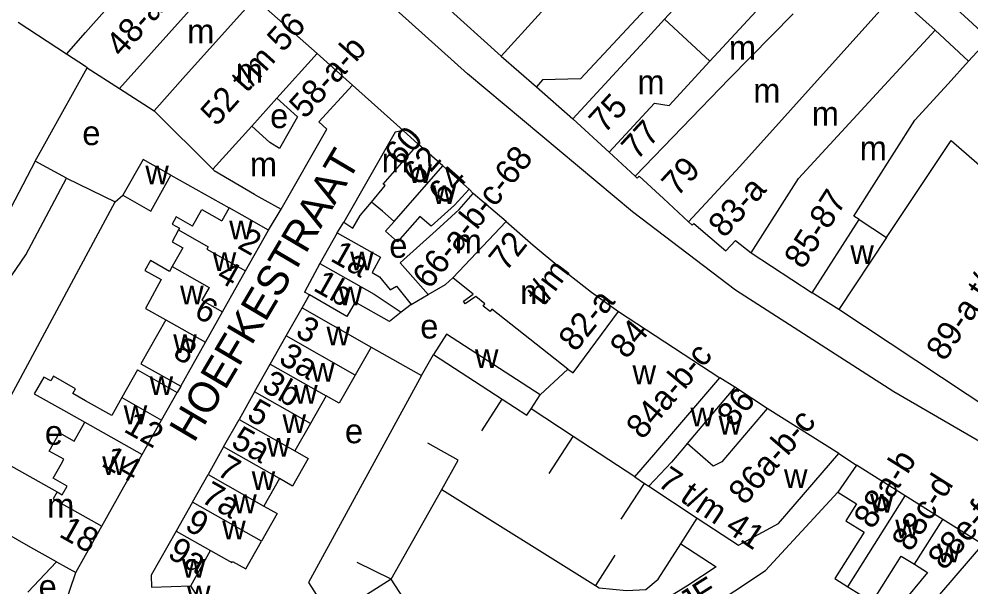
# Model space of a CAD drawing. Extents: x 161141 to 163125, y 381621 to 383200.
# Drawn here: x 161989.1 to 162145.3, y 382642.8 to 382736 of the extents above; entities that cross this region are included whole.
import ezdxf

# ---------------------------------------------------------------- set-up
doc = ezdxf.new("R2010")
doc.units = 0
for name, color, linetype in [('BLT_Basislijn', 7, 'Continuous'), ('BLT_Bebouwing', 7, 'Continuous'), ('BLT_Centroide', 7, 'Continuous'), ('BLT_Huisnummer', 7, 'Continuous'), ('BLT_Huisnummer_ tussenligend', 7, 'Continuous'), ('BLT_Huisnummer_reeks', 7, 'Continuous'), ('BLT_Onderdoorgang_en_onderverdeling', 7, 'Continuous'), ('BLT_Onderverdeling_panden', 7, 'Continuous'), ('BLT_Straatnaam', 7, 'Continuous'), ('BLT_Straatnaam_verkleind', 7, 'Continuous'), ('BLT_Vlakafsluiter', 7, 'Continuous')]:
    doc.layers.add(name, color=color, linetype=linetype)

msp = doc.modelspace()

# ---------------------------------------------------------------- linework, layer by layer
at = {"layer": 'BLT_Basislijn'}
for p, q in [((161996.85, 382730.23), (161988.94, 382735.42)), ((162091.73, 382732.39), (162095.04, 382735.97)), ((162144.96, 382729.08), (162148.35, 382732.76)), ((162068.23, 382729.9), (162074, 382724.85)), ((161991.75, 382712.66), (162000.28, 382728.01)), ((162074, 382724.85), (162079.97, 382719.63)), ((161996.85, 382709.9), (162004.85, 382706.01)), ((162014.02, 382710.39), (162023.55, 382705.02)), ((162004.85, 382706.01), (162006.11, 382707.09)), ((162062.96, 382708.09), (162063.65, 382707.38)), ((162030.05, 382701.36), (162032.1, 382704.77)), ((162041.29, 382700.91), (162042.39, 382702.67)), ((162035.54, 382688.59), (162036.76, 382690.71)), ((162053.43, 382689.16), (162056.23, 382690.77)), ((162046.91, 382682.16), (162055.13, 382677.47)), ((162055.13, 382677.47), (162057.1, 382680.93)), ((162015.62, 382675.73), (162015.05, 382674.72)), ((162065.03, 382668.42), (162068.39, 382673.6)), ((162076.1, 382661.41), (162080.07, 382667.46)), ((162123.64, 382664.66), (162126.56, 382662.79)), ((162087.91, 382653.91), (162091.77, 382659.78)), ((162058.5, 382658.78), (162083.69, 382643.01)), ((162097.73, 382649.88), (162100.42, 382654.1)), ((162097.73, 382649.88), (162103.51, 382646.09)), ((162086.88, 382648.01), (162083.69, 382643.01)), ((161995.24, 382646.9), (161990.55, 382641.9)), ((162050.15, 382644.06), (162044.6, 382646.82)), ((161994.61, 382633.9), (161998.38, 382645.14)), ((162050.15, 382644.06), (162044.91, 382640.75))]:
    msp.add_line(p, q, dxfattribs=at)
for points in [[(162102.69, 382767.58), (162109.46, 382761.98), (162109.6, 382759.03), (162107.87, 382754.82), (162081.25, 382726.17), (162075.01, 382726.01), (162074, 382724.85)], [(162194.06, 382643.33), (162189.92, 382645.12), (162160.02, 382658.95), (162132.67, 382674.8), (162106.7, 382691.49), (162089.78, 382704.36), (162062.68, 382727.01), (162023.66, 382762.05), (162018.44, 382766.74)], [(162140.88, 382739.62), (162148.35, 382732.76)], [(161984.01, 382653.23), (161978.86, 382656.23), (161978.54, 382657.06), (162004.85, 382706.01)], [(162055.13, 382677.47), (162036.62, 382643.49), (162049.02, 382624.08), (162038.63, 382617.36)], [(162058.5, 382658.78), (162061.17, 382663.57), (162056.17, 382666.36)], [(162050.15, 382644.06), (162058.5, 382658.78)], [(162077.14, 382623.58), (162080.5, 382625.73), (162083.75, 382627.77), (162101.57, 382638.79), (162111.63, 382645.49), (162123.49, 382658.34)], [(162083.69, 382643.01), (162084.3, 382642.64), (162088.8, 382642.18), (162092, 382642.38), (162094.02, 382644.07), (162097.73, 382649.88)], [(162103.51, 382646.09), (162098.87, 382643), (162081.1, 382632.01), (162077.82, 382629.96), (162074.45, 382627.79)], [(162053.55, 382627.28), (162058.87, 382630.64), (162050.15, 382644.06)]]:
    msp.add_lwpolyline(points, dxfattribs=at)
at = {"layer": 'BLT_Bebouwing'}
for p, q in [((162038.01, 382730.34), (162027.8, 382739.4)), ((162058.74, 382738.42), (162068.23, 382729.9)), ((162095.04, 382735.97), (162091.73, 382732.39)), ((162139.45, 382734.15), (162144.96, 382729.08)), ((162091.73, 382732.39), (162079.97, 382719.63)), ((162043.81, 382725.15), (162038.01, 382730.34)), ((162000.28, 382728.01), (162005.58, 382724.59)), ((162005.58, 382724.59), (162011.25, 382720.93)), ((162027.28, 382718.42), (162031.39, 382722.99)), ((162011.25, 382720.93), (162020.9, 382711.33)), ((162079.97, 382719.63), (162085.93, 382714.15)), ((162054.62, 382715.47), (162052.13, 382717.68)), ((162058.67, 382711.89), (162054.62, 382715.47)), ((161996.85, 382709.9), (161991.75, 382712.66)), ((162062.96, 382708.09), (162058.67, 382711.89)), ((162090.88, 382710.22), (162094.85, 382706.54)), ((162027.86, 382707.16), (162032.1, 382704.77)), ((162023.55, 382705.02), (162022.35, 382702.89)), ((162069.02, 382702.77), (162073.46, 382698.87)), ((162099.83, 382702.42), (162105.08, 382697.93)), ((162126.98, 382703.12), (162131.49, 382700.13)), ((162026.27, 382694.66), (162030.05, 382701.36)), ((162041.29, 382700.91), (162038.45, 382695.88)), ((162073.46, 382698.87), (162078, 382695.11)), ((162038.45, 382695.88), (162035.92, 382691.19)), ((162022.48, 382687.93), (162026.27, 382694.66)), ((162078, 382695.11), (162083.04, 382691.16)), ((162083.04, 382691.16), (162087.49, 382688.01)), ((162123.64, 382688.31), (162119.3, 382691.06)), ((162019.68, 382682.96), (162022.48, 382687.93)), ((162032.95, 382684), (162035.54, 382688.59)), ((162035.54, 382688.59), (162046.91, 382682.16)), ((162053.43, 382689.16), (162051.79, 382687.86)), ((162079.18, 382678.52), (162066.72, 382688.36)), ((162087.49, 382688.01), (162104.12, 382677.11)), ((162155.14, 382667.45), (162123.64, 382688.31)), ((162013.16, 382686.64), (162009.09, 382679.41)), ((162030.32, 382679.34), (162032.95, 382684)), ((162059.27, 382684.29), (162057.1, 382680.93)), ((162074.63, 382674.32), (162059.27, 382684.29)), ((162015.62, 382675.73), (162019.68, 382682.96)), ((162046.91, 382682.16), (162044.28, 382677.54)), ((162057.1, 382680.93), (162068.39, 382673.6)), ((162009.09, 382679.41), (162015.62, 382675.73)), ((162027.76, 382674.81), (162030.32, 382679.34)), ((162074.63, 382674.32), (162079.18, 382678.52)), ((162008.52, 382678.41), (162015.05, 382674.72)), ((162044.28, 382677.54), (162041.65, 382672.93)), ((162106.6, 382675.55), (162104.12, 382677.11)), ((162111.91, 382672.09), (162106.6, 382675.55)), ((162012.49, 382670.18), (162015.05, 382674.72)), ((162027.76, 382674.81), (162025.21, 382670.28)), ((162039.48, 382674.16), (162036.93, 382669.63)), ((162041.65, 382672.93), (162039.48, 382674.16)), ((162068.39, 382673.6), (162072.45, 382670.97)), ((162072.45, 382670.97), (162073.13, 382672.01)), ((162080.07, 382667.46), (162073.13, 382672.01)), ((162123.64, 382664.66), (162111.91, 382672.09)), ((162009.3, 382664.52), (162012.49, 382670.18)), ((162022.66, 382665.77), (162025.21, 382670.28)), ((162036.93, 382669.63), (162034.37, 382665.11)), ((162090.17, 382660.83), (162080.07, 382667.46)), ((162006.31, 382659.21), (162009.3, 382664.52)), ((162022.66, 382665.77), (162020.11, 382661.23)), ((162113.76, 382653.2), (162123.64, 382664.66)), ((162017.55, 382656.7), (162020.11, 382661.23)), ((162126.56, 382662.79), (162123.49, 382658.34)), ((162134.54, 382657.75), (162126.56, 382662.79)), ((162031.82, 382660.59), (162029.26, 382656.06)), ((162090.17, 382660.83), (162091.77, 382659.78)), ((162091.77, 382659.78), (162092.46, 382659.32)), ((162002.67, 382652.74), (162006.31, 382659.21)), ((162092.46, 382659.32), (162100.42, 382654.1)), ((162017.55, 382656.7), (162014.86, 382651.93)), ((162140.71, 382653.86), (162134.54, 382657.75)), ((162100.42, 382654.1), (162107.21, 382649.64)), ((162147.32, 382649.73), (162140.71, 382653.86)), ((162014.86, 382651.93), (162010.79, 382644.71)), ((162107.21, 382649.64), (162113.76, 382653.2)), ((162017.27, 382642.97), (162020.52, 382648.76)), ((162020.52, 382648.76), (162024.02, 382646.8)), ((162134.66, 382635.1), (162147.32, 382649.73)), ((161995.24, 382646.9), (161998.38, 382645.14)), ((162010.79, 382644.71), (162010.84, 382642.76)), ((162020.91, 382637.37), (162017.27, 382642.97))]:
    msp.add_line(p, q, dxfattribs=at)
for points in [[(162068.23, 382729.9), (162086.47, 382750), (162102.69, 382767.58)], [(162121.93, 382750.12), (162114.43, 382756.97), (162107.96, 382750), (162095.04, 382735.97)], [(162132.85, 382740.14), (162139.45, 382734.15)], [(161996.85, 382730.23), (162000, 382733.78), (162003.56, 382737.77)], [(162000.28, 382728.01), (162000, 382728.2), (161996.85, 382730.23)], [(162126.98, 382703.12), (162126.14, 382703.65), (162136.15, 382719.38), (162141.6, 382725.38), (162144.96, 382729.08)], [(162032.1, 382704.77), (162039.61, 382717.92), (162038.32, 382719.11), (162043.81, 382725.15)], [(162031.39, 382722.99), (162034.81, 382719.92), (162031.86, 382714.76)], [(162031.86, 382714.76), (162030.26, 382715.75), (162027.28, 382718.42)], [(162052.13, 382717.68), (162050.83, 382717.45), (162042.39, 382702.67)], [(162131.49, 382700.13), (162142.07, 382716.04), (162148.8, 382710.21)], [(162014.02, 382710.39), (162009.45, 382712.96), (162006.11, 382707.09)], [(162085.93, 382714.15), (162090.2, 382710.23)], [(161991.75, 382712.66), (161985, 382699.88), (161979.85, 382692.38)], [(162020.9, 382711.33), (162021.09, 382711.15), (162027.74, 382707.23), (162027.86, 382707.16)], [(161963.29, 382667.06), (161980.34, 382682.94), (161990.19, 382697.3), (161996.85, 382709.9)], [(162006.11, 382707.09), (162010.72, 382704.49), (162014.02, 382710.39)], [(162090.2, 382710.23), (162090.57, 382709.89), (162090.88, 382710.22)], [(162062.96, 382708.09), (162060.54, 382705.43), (162056.72, 382702), (162054.89, 382703.61), (162051.23, 382699.45), (162049.26, 382701.18), (162050.67, 382702.79)], [(162056.23, 382690.77), (162051.67, 382695.98), (162057.54, 382701.28), (162061.34, 382704.75), (162063.65, 382707.38)], [(162069.02, 382702.77), (162063.65, 382707.38)], [(162030.05, 382701.36), (162025.7, 382703.81), (162023.55, 382705.02)], [(162042.39, 382702.67), (162043.89, 382701.66), (162045.08, 382703.76), (162046.96, 382705.95)], [(162050.67, 382702.79), (162048.76, 382704.47), (162046.96, 382705.95)], [(162094.85, 382706.54), (162099, 382702.69)], [(162017.57, 382701.98), (162014.85, 382703.51), (162014.23, 382702.34), (162015.4, 382701.67), (162015.25, 382701.38)], [(162017.57, 382701.98), (162019.11, 382704.71), (162022.35, 382702.89)], [(162099, 382702.69), (162099.58, 382702.15), (162099.83, 382702.42)], [(162015.25, 382701.38), (162014.23, 382699.45), (162015.97, 382698.47), (162014.22, 382695.37)], [(162041.29, 382700.91), (162048.43, 382696.89), (162047.03, 382694.41), (162048.27, 382693.7), (162050.03, 382691.55), (162051.02, 382692.14), (162053.43, 382689.16)], [(162105.08, 382697.93), (162106.67, 382699.66), (162109.25, 382697.6)], [(162109.25, 382697.6), (162119.3, 382691.06)], [(162014.22, 382695.37), (162013.78, 382694.58), (162010.64, 382696.34), (162009.74, 382694.73), (162012.4, 382693.23), (162009.86, 382688.49), (162013.16, 382686.64)], [(162056.23, 382690.77), (162059.11, 382692.41), (162060.29, 382693.5)], [(162066.72, 382688.36), (162066.4, 382687.98), (162065.26, 382688.89), (162065.57, 382689.27), (162064.07, 382690.47), (162062.34, 382689.28), (162062.04, 382689.71), (162063.64, 382690.82), (162060.29, 382693.5)], [(162036.76, 382690.71), (162035.92, 382691.19)], [(162051.79, 382687.86), (162049.9, 382686.35), (162044.24, 382689.53), (162042.9, 382687.16), (162036.76, 382690.71)], [(162005.96, 382673.86), (162004.31, 382670.93), (162000, 382673.33), (161997.9, 382674.51), (161998.36, 382675.31), (161994.73, 382677.36), (161994.3, 382676.59), (161993.13, 382677.24), (161991.57, 382674.48), (161996.37, 382671.78), (161999.86, 382669.82)], [(162008.52, 382678.41), (162005.96, 382673.86)], [(161995.99, 382662.95), (161996.42, 382663.73), (161994.03, 382665.07), (161995.73, 382668.07), (161998.12, 382666.73), (161999.86, 382669.82)], [(162034.37, 382665.11), (162036.56, 382663.87), (162033.99, 382659.35), (162031.82, 382660.59)], [(161984.01, 382653.23), (161987.4, 382659.25), (161985.32, 382660.42), (161986.86, 382663.16), (161995.36, 382658.38)], [(161995.36, 382658.38), (161996.17, 382657.92), (161996.97, 382659.35), (161994.68, 382660.63), (161995.99, 382662.95)], [(162123.49, 382658.34), (162126.57, 382656.4), (162124.82, 382653.63), (162127.8, 382651.75), (162123.01, 382644.15), (162125.12, 382642.81)], [(162029.26, 382656.06), (162031.43, 382654.83), (162028.87, 382650.3)], [(161995.24, 382646.9), (161991.02, 382649.28), (161984.01, 382653.23)], [(161998.38, 382645.14), (162000, 382648.01), (162002.67, 382652.74)], [(162024.02, 382646.8), (162024.12, 382646.98), (162026.3, 382645.77), (162028.87, 382650.3)], [(162125.12, 382642.81), (162127.24, 382641.48), (162129.13, 382640.29), (162133.9, 382647.86), (162136.06, 382646.5)], [(162136.06, 382646.5), (162138.22, 382645.13), (162133.76, 382639.8), (162135, 382638.75), (162133.06, 382636.46), (162134.66, 382635.1)]]:
    msp.add_lwpolyline(points, dxfattribs=at)
at = {"layer": 'BLT_Onderdoorgang_en_onderverdeling'}
msp.add_line((162106.6, 382675.55), (162098.77, 382666.32), dxfattribs=at)
for points in [[(162090.17, 382660.83), (162093.6, 382664.83), (162104.12, 382677.11)], [(162098.77, 382666.32), (162098.04, 382665.46), (162096.17, 382663.25), (162092.46, 382659.32)]]:
    msp.add_lwpolyline(points, dxfattribs=at)
at = {"layer": 'BLT_Onderverdeling_panden'}
for p, q in [((162121.93, 382750.12), (162102.5, 382729.1)), ((162022.84, 382743.85), (162011.25, 382730.92)), ((162027.8, 382739.4), (162016.43, 382726.71)), ((162132.85, 382740.14), (162107.39, 382711.82)), ((162095.04, 382735.97), (162102.5, 382729.1)), ((162117.03, 382709.81), (162139.45, 382734.15)), ((162011.25, 382730.92), (162005.58, 382724.59)), ((162038.01, 382730.34), (162031.39, 382722.99)), ((162016.43, 382726.71), (162011.25, 382720.93)), ((162020.9, 382711.33), (162027.28, 382718.42)), ((162050.67, 382702.79), (162058.67, 382711.89)), ((162099, 382702.69), (162107.39, 382711.82)), ((162069.02, 382702.77), (162060.29, 382693.5)), ((162119.3, 382691.06), (162126.98, 382703.12)), ((162131.49, 382700.13), (162123.64, 382688.31)), ((162013.16, 382686.64), (162019.68, 382682.96)), ((162044.28, 382677.54), (162032.95, 382684)), ((162030.32, 382679.34), (162039.48, 382674.16)), ((162005.96, 382673.86), (162012.49, 382670.18)), ((162036.93, 382669.63), (162027.76, 382674.81)), ((161999.86, 382669.82), (162009.3, 382664.52)), ((162025.21, 382670.28), (162034.37, 382665.11)), ((162031.82, 382660.59), (162022.66, 382665.77)), ((162020.11, 382661.23), (162029.26, 382656.06)), ((162028.87, 382650.3), (162017.55, 382656.7)), ((162125.12, 382642.81), (162134.54, 382657.75)), ((162136.06, 382646.5), (162140.71, 382653.86)), ((162014.86, 382651.93), (162020.52, 382648.76)), ((162010.84, 382642.76), (162017.27, 382642.97))]:
    msp.add_line(p, q, dxfattribs=at)
for points in [[(162116.14, 382736.83), (162105.63, 382726.21), (162090.2, 382710.23)], [(162085.93, 382714.15), (162093.39, 382722.2), (162095.79, 382721.83), (162102.5, 382729.1)], [(162046.96, 382705.95), (162049.17, 382708.65), (162048.86, 382708.92), (162054.62, 382715.47)], [(162109.25, 382697.6), (162117.03, 382709.81)], [(162015.25, 382701.38), (162020.12, 382698.61), (162019.91, 382698.24), (162026.27, 382694.66)], [(162038.45, 382695.88), (162047.4, 382690.84), (162051.79, 382687.86)], [(162014.22, 382695.37), (162020.28, 382691.96), (162019.09, 382689.84), (162022.48, 382687.93)], [(162079.18, 382678.52), (162080.06, 382677.95), (162087.49, 382688.01)], [(162073.13, 382672.01), (162074.63, 382674.32)], [(162111.91, 382672.09), (162104.44, 382663.34), (162103.04, 382662.59), (162098.77, 382666.32)], [(161995.36, 382658.38), (161994.71, 382657.22), (162002.67, 382652.74)]]:
    msp.add_lwpolyline(points, dxfattribs=at)
at = {"layer": 'BLT_Vlakafsluiter'}
msp.add_line((162043.81, 382725.15), (162052.13, 382717.68), dxfattribs=at)

# ---------------------------------------------------------------- texts
at = {"layer": 'BLT_Centroide'}
for s, p in [('m', (162016.69, 382732)), ('m', (162105.61, 382729.31)), ('m', (162024.67, 382725.53)), ('m', (162090.59, 382723.66)), ('m', (162109.61, 382722.27)), ('e', (162030.3, 382718.1)), ('m', (162119.22, 382718.48)), ('e', (161999.47, 382715.3)), ('m', (162127.08, 382712.81)), ('m', (162026.98, 382710.17)), ('m', (162048.61, 382710.83)), ('w', (162009.81, 382708.88)), ('w', (162052.98, 382709.06)), ('w', (162056.95, 382705.62)), ('w', (162023.58, 382699.84)), ('m', (162060.61, 382697.53)), ('e', (162049.86, 382696.81)), ('w', (162125.54, 382695.8)), ('w', (162020.88, 382694.66)), ('w', (162043.43, 382694.77)), ('w', (162015.52, 382689.16)), ('w', (162041.53, 382689)), ('m', (162071.34, 382689.2)), ('e', (162054.94, 382683.56)), ('w', (162039.56, 382682.42)), ('w', (162014.39, 382681.19)), ('w', (162063.92, 382678.73)), ('w', (162037.03, 382676.47)), ('w', (162089.79, 382676.06)), ('w', (162010.51, 382674.28)), ('w', (162034.24, 382672.86)), ('w', (162006.26, 382669.5)), ('w', (162099.3, 382669.14)), ('w', (162032.33, 382668.05)), ('w', (162103.91, 382667.8)), ('e', (161993.32, 382666.11)), ('e', (162042.58, 382666.37)), ('w', (162029.74, 382664.18)), ('w', (162002.73, 382661.17)), ('w', (162027.27, 382658.71)), ('w', (162114.65, 382659.02)), ('m', (161993.7, 382654.16)), ('w', (162024.24, 382654.89)), ('w', (162128.78, 382654.98)), ('w', (162022.43, 382650.6)), ('w', (162132.92, 382650.75)), ('w', (162139.81, 382646.81)), ('w', (162015.83, 382644.28)), ('e', (161992.3, 382640.83)), ('w', (162016.65, 382639.91))]:
    msp.add_text(s, height=4, dxfattribs=at).set_placement(p)
at = {"layer": 'BLT_Huisnummer'}
for s, rotation, p in [('75', 47.4102, (162085.19, 382717.05)), ('60', 48.6828, (162051.68, 382711.66)), ('79', 47.4316, (162097.13, 382706.7)), ('64', 48.6817, (162058.9, 382705.26)), ('2', 330.6144, (162024.76, 382698.5)), ('1a', 330.5914, (162040, 382696.41)), ('1b', 330.5977, (162037.19, 382691.55)), ('3', 330.4232, (162034.25, 382684.07)), ('8', 330.6156, (162014.13, 382680.59)), ('3a', 330.4232, (162031.49, 382679.62)), ('3b', 330.4232, (162028.7, 382675.11)), ('86', 50.7529, (162106.39, 382668.78)), ('5', 330.4232, (162026.26, 382670.42)), ('12', 330.6089, (162006.08, 382668.37)), ('5a', 330.4232, (162023.67, 382665.93)), ('7', 330.4232, (162021.32, 382661.28)), ('7a', 330.4232, (162018.73, 382656.85)), ('9', 330.4232, (162016.09, 382652.32)), ('18', 330.6134, (161995.46, 382651.14)), ('9a', 330.4232, (162013.26, 382647.71))]:
    msp.add_text(s, height=4, rotation=rotation, dxfattribs=at).set_placement(p)
at = {"layer": 'BLT_Huisnummer_ tussenligend'}
for s, rotation, p in [('77', 47.2949, (162090.52, 382712.68)), ('62', 48.6828, (162054.68, 382708.44)), ('4', 330.6144, (162021.29, 382693.2)), ('6', 330.6156, (162017.59, 382687.29)), ('14', 330.606, (162002.41, 382662.73))]:
    msp.add_text(s, height=4, rotation=rotation, dxfattribs=at).set_placement(p)
at = {"layer": 'BLT_Huisnummer_reeks'}
for s, rotation, p in [('48-a t/m d', 48.2219, (162005.94, 382729.55)), ('52 t/m 56', 48.1307, (162021.49, 382718.23)), ('58-a-b', 48.2242, (162036.02, 382719.46)), ('66-a-b-c-68', 51.5635, (162056.45, 382691.48)), ('89-a t/m 101-a', 56.4901, (162141.03, 382679.67)), ('83-a', 48.3328, (162104.84, 382699.9)), ('85-87', 57.5212, (162117.77, 382694.77)), ('72', 51.5635, (162069, 382694.39)), ('t/m', 52.9041, (162075.2, 382688.66)), ('82-a', 51.5635, (162080.44, 382681.21)), ('84', 50.0897, (162088.8, 382680.01)), ('84a-b-c', 50.0897, (162091.45, 382666.8)), ('86a-b-c', 49.2245, (162108.22, 382656.05)), ('88a-b', 57.7697, (162129.21, 382652.09)), ('7 t/m 41', 326.0897, (162093.68, 382659.51)), ('88c-d', 57.7583, (162135.45, 382648.37)), ('88e-f', 49.6663, (162140.97, 382645.34))]:
    msp.add_text(s, height=4, rotation=rotation, dxfattribs=at).set_placement(p)
at = {"layer": 'BLT_Straatnaam'}
msp.add_text('HOEFKESTRAAT', height=5, rotation=59.435, dxfattribs=at).set_placement((162017.8, 382666.29))
at = {"layer": 'BLT_Straatnaam_verkleind'}
msp.add_text('ST ROCHUSHOFJE', height=4, rotation=32.1959, dxfattribs=at).set_placement((162062.82, 382615.23))

doc.saveas('drawing.dxf')
